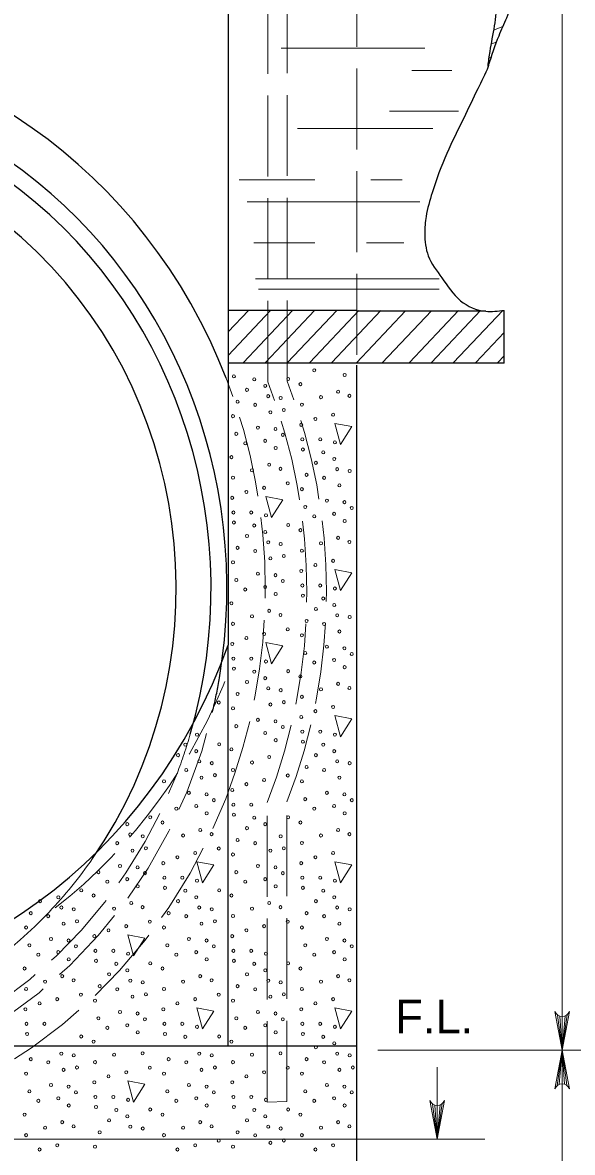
# Model space of a CAD drawing. Extents: x 1329.9 to 1363.9, y 715.5 to 737.5.
# Drawn here: x 1336.95 to 1339.48, y 718.65 to 723.85 of the extents above; entities that cross this region are included whole.
import ezdxf

# ---------------------------------------------------------------- set-up
doc = ezdxf.new("R2010")
doc.units = 0
doc.header["$LTSCALE"] = 0.062
doc.linetypes.add('LONG_DASHED', pattern=[7.5, 6, -1.5])
doc.layers.add('1', color=7, linetype='Continuous', lineweight=13)

msp = doc.modelspace()

# ---------------------------------------------------------------- linework, layer by layer
at = {"layer": '1', "linetype": 'LONG_DASHED'}
for p, q in [((1338.07492, 722.19533), (1338.07492, 728.64683)), ((1338.16467, 722.19817), (1338.16467, 728.66258)), ((1338.4845, 722.32), (1338.4845, 724.47975)), ((1338.07242, 718.88408), (1338.07242, 720.26208)), ((1338.16217, 718.88683), (1338.16217, 720.26483))]:
    msp.add_line(p, q, dxfattribs=at)
at = {"layer": '1'}
for p, q in [((1339.42875, 719.1235), (1339.42875, 725.87033)), ((1339.113, 723.81283), (1339.15642, 723.82967)), ((1338.1365, 723.73), (1338.797, 723.73)), ((1339.10158, 723.74783), (1339.12858, 723.75825)), ((1339.09125, 723.68325), (1339.104, 723.68817)), ((1338.73767, 723.6275), (1338.92117, 723.6275)), ((1339.087, 723.65125), (1339.09108, 723.65283)), ((1338.63417, 723.43925), (1338.95258, 723.43925)), ((1338.21075, 723.36067), (1338.83417, 723.36067)), ((1337.9435, 723.12492), (1338.29117, 723.12492)), ((1338.54842, 723.12492), (1338.69308, 723.12492)), ((1337.98067, 723.02283), (1338.77475, 723.02283)), ((1338.01033, 722.83417), (1338.29117, 722.83417)), ((1338.52942, 722.83417), (1338.70058, 722.83417)), ((1338.01775, 722.66917), (1338.8635, 722.66917)), ((1338.03258, 722.62208), (1338.8635, 722.62208)), ((1337.892, 722.3175), (1338.08733, 722.52442)), ((1337.892, 722.425), (1337.98592, 722.52442)), ((1337.892, 722.5205), (1337.89942, 722.52333)), ((1337.963, 722.28517), (1338.18892, 722.52442)), ((1338.0645, 722.28517), (1338.29042, 722.52442)), ((1338.16592, 722.28517), (1338.39192, 722.52442)), ((1338.2675, 722.28517), (1338.49342, 722.52442)), ((1338.36892, 722.28517), (1338.59492, 722.52442)), ((1338.48258, 722.28242), (1338.70858, 722.52167)), ((1338.60158, 722.28233), (1338.82758, 722.52158)), ((1338.7265, 722.28517), (1338.95233, 722.52433)), ((1338.82792, 722.28517), (1339.05383, 722.52433)), ((1338.92942, 722.28517), (1339.15533, 722.52433)), ((1339.031, 722.28517), (1339.16133, 722.42325)), ((1339.13242, 722.28517), (1339.16133, 722.31575)), ((1339.40742, 719.28467), (1339.42875, 719.1235)), ((1339.41792, 719.27925), (1339.42875, 719.1235)), ((1339.45225, 719.28658), (1339.42875, 719.1235)), ((1339.44242, 719.28042), (1339.42875, 719.1235)), ((1339.42875, 719.27758), (1339.42875, 719.1235)), ((1339.96792, 719.1235), (1338.58108, 719.1235)), ((1339.40517, 718.96033), (1339.42875, 719.1235)), ((1339.415, 718.9665), (1339.42875, 719.1235)), ((1339.42875, 719.1235), (1339.42875, 717.1515)), ((1339.42875, 718.96933), (1339.42875, 719.1235)), ((1339.4395, 718.96767), (1339.42875, 719.1235)), ((1339.45, 718.96225), (1339.42875, 719.1235)), ((1338.85383, 719.04492), (1338.85383, 718.71467)), ((1338.07242, 718.88408), (1338.16217, 718.88683)), ((1338.83258, 718.87592), (1338.85383, 718.71467)), ((1338.84308, 718.8705), (1338.85383, 718.71467)), ((1338.87742, 718.87783), (1338.85383, 718.71467)), ((1338.8675, 718.87167), (1338.85383, 718.71467)), ((1338.85383, 718.86883), (1338.85383, 718.71467)), ((1338.85383, 718.71467), (1336.15375, 718.71467)), ((1339.0725, 718.71467), (1338.84275, 718.71467))]:
    msp.add_line(p, q, dxfattribs=at)
at = {"layer": '1', "lineweight": 25}
for p, q in [((1337.892, 724.68033), (1337.892, 720.98492)), ((1338.4845, 722.52433), (1337.892, 722.52433)), ((1339.077, 722.52025), (1338.4845, 722.52025)), ((1339.16133, 722.28192), (1339.16133, 722.52433)), ((1339.16133, 722.28192), (1337.892, 722.28192)), ((1338.4845, 718.46475), (1338.4845, 722.27233)), ((1337.89108, 720.98492), (1337.89108, 719.143)), ((1332.86792, 719.143), (1338.4845, 719.143))]:
    msp.add_line(p, q, dxfattribs=at)
at = {"layer": '1'}
for points in [[(1338.38283, 722.00483), (1338.4085, 721.90758), (1338.46067, 721.98975)], [(1338.06558, 721.66908), (1338.09125, 721.57167), (1338.1435, 721.65383)], [(1338.38283, 721.33317), (1338.4085, 721.23583), (1338.46067, 721.318)], [(1338.06558, 720.99733), (1338.09125, 720.90008), (1338.1435, 720.98225)], [(1338.38283, 720.66158), (1338.4085, 720.56425), (1338.46067, 720.64642)], [(1337.74842, 719.98992), (1337.774, 719.89258), (1337.82633, 719.97475)], [(1338.38283, 719.98992), (1338.4085, 719.89258), (1338.46067, 719.97475)], [(1337.43125, 719.65408), (1337.45692, 719.55675), (1337.50908, 719.63892)], [(1337.74842, 719.31825), (1337.774, 719.22092), (1337.82633, 719.30317)], [(1338.38283, 719.31825), (1338.4085, 719.22092), (1338.46067, 719.30317)], [(1337.43125, 718.9825), (1337.45692, 718.88517), (1337.50908, 718.96725)]]:
    msp.add_lwpolyline(points, close=True, dxfattribs=at)
for points in [[(1339.46233, 719.30158), (1339.42875, 719.1235), (1339.39508, 719.30158)], [(1339.39508, 718.94533), (1339.42875, 719.1235), (1339.46233, 718.94533)], [(1338.8875, 718.89283), (1338.85383, 718.71467), (1338.82025, 718.89283)]]:
    msp.add_lwpolyline(points, dxfattribs=at)
at = {"layer": '1', "lineweight": 25}
for centre, major_axis, start_param, end_param in [((1335.66941, 721.24918), (0, -2.53448), 1.9607306, 4.343612), ((1335.66941, 721.24721), (0, -2.34775), 1.3944021, 4.9078414), ((1335.66941, 721.24578), (0, 2.27026), 4.4130472, 8.1227679), ((1335.66941, 721.24721), (0, 2.1004), 4.0791732, 8.4607413), ((1335.66522, 721.87991), (0, -2.52169), 5.0813574, 7.4910277)]:
    msp.add_ellipse(centre, major_axis=major_axis, ratio=0.944544, start_param=start_param, end_param=end_param, dxfattribs=at)
at = {"layer": '1'}
for centre in [(1337.91918, 722.22062), (1338.2884, 722.24872), (1338.42828, 722.22756), (1338.01259, 722.20702), (1338.06308, 722.17707), (1338.16844, 722.20881), (1338.22496, 722.18525), (1337.97913, 722.15894), (1338.07682, 722.12995), (1338.13418, 722.12172), (1338.31948, 722.12513), (1338.3983, 722.15049), (1338.45054, 722.13146), (1337.93604, 722.10426), (1338.01682, 722.09004), (1338.14872, 722.06648), (1338.23183, 722.09088), (1337.91463, 722.03804), (1338.08703, 722.05556), (1338.29373, 722.02534), (1338.37515, 722.04437), (1338.0294, 721.98549), (1338.11024, 721.97849), (1338.22871, 721.99814), (1337.93007, 721.95644), (1337.9712, 721.91289), (1338.06281, 721.9247), (1338.14391, 721.9519), (1338.23384, 721.93103), (1338.3161, 721.93103), (1338.38371, 721.91743), (1338.11108, 721.89174), (1338.23637, 721.8848), (1338.32979, 721.8712), (1337.90776, 721.84942), (1338.08111, 721.81466), (1338.29633, 721.82312), (1338.38028, 721.84125), (1337.91463, 721.75506), (1338.00228, 721.78931), (1338.13334, 721.79563), (1338.25324, 721.76843), (1338.33402, 721.75422), (1338.39402, 721.79412), (1338.45138, 721.7859), (1338.05795, 721.70854), (1338.1667, 721.72942), (1338.23183, 721.70222), (1338.40423, 721.71974), (1337.91151, 721.66231), (1337.97654, 721.68951), (1338.3466, 721.64966), (1337.91664, 721.5952), (1337.9989, 721.5952), (1338.24727, 721.62062), (1338.42743, 721.64267), (1338.46111, 721.61608), (1337.91918, 721.54897), (1338.06651, 721.5816), (1338.2884, 721.57707), (1338.38001, 721.58888), (1338.42828, 721.55591), (1338.01259, 721.53537), (1338.06308, 721.50543), (1338.16844, 721.53716), (1338.22496, 721.5136), (1337.97913, 721.48729), (1338.07682, 721.4583), (1338.13418, 721.45007), (1338.31948, 721.45349), (1338.3983, 721.47884), (1338.45054, 721.45981), (1337.93604, 721.43261), (1338.01682, 721.41839), (1338.14872, 721.39483), (1338.23183, 721.41923), (1337.91463, 721.3664), (1338.08703, 721.38392), (1338.29373, 721.35369), (1338.37515, 721.37272), (1337.93007, 721.28479), (1338.0294, 721.31384), (1338.11024, 721.30684), (1338.22871, 721.32649), (1337.9712, 721.24125), (1338.06281, 721.25306), (1338.14391, 721.28026), (1338.23384, 721.25938), (1338.3161, 721.25938), (1338.38371, 721.24578), (1337.90776, 721.17778), (1338.11108, 721.22009), (1338.23637, 721.21315), (1338.32979, 721.19955), (1338.08111, 721.14302), (1338.29633, 721.15147), (1338.38028, 721.16961), (1337.91463, 721.08341), (1338.00228, 721.11766), (1338.13334, 721.12399), (1338.25324, 721.09679), (1338.33402, 721.08257), (1338.39402, 721.12248), (1338.45138, 721.11425), (1338.05795, 721.0369), (1338.1667, 721.05778), (1338.23183, 721.03057), (1338.40423, 721.04809), (1337.91151, 720.99067), (1337.97654, 721.01787), (1338.3466, 720.97802), (1338.42743, 720.97102), (1337.91664, 720.92356), (1337.9989, 720.92356), (1338.24727, 720.94897), (1338.46111, 720.94444), (1337.91918, 720.87733), (1338.06651, 720.90996), (1338.2884, 720.90542), (1338.38001, 720.91723), (1338.42828, 720.88427), (1337.97913, 720.81565), (1338.01259, 720.86373), (1338.06308, 720.83378), (1338.16844, 720.86552), (1338.22496, 720.84195), (1338.07682, 720.78666), (1338.13418, 720.77843), (1338.31948, 720.78184), (1338.3983, 720.8072), (1338.45054, 720.78817), (1337.8495, 720.72195), (1337.93604, 720.76096), (1338.08703, 720.71227), (1338.14872, 720.72318), (1338.23183, 720.74759), (1337.91463, 720.69475), (1338.29373, 720.68205), (1338.37515, 720.70108), (1337.93007, 720.61315), (1338.0294, 720.6422), (1338.11024, 720.6352), (1338.14391, 720.60861), (1338.22871, 720.65484), (1337.74932, 720.57414), (1338.06281, 720.58141), (1338.23384, 720.58774), (1338.3161, 720.58774), (1338.38371, 720.57414), (1337.69539, 720.5279), (1337.85124, 720.52969), (1337.90776, 720.50613), (1338.11108, 720.54845), (1338.23637, 720.5415), (1338.32979, 720.5279), (1337.66193, 720.47983), (1337.74588, 720.49796), (1337.75962, 720.45083), (1338.08111, 720.47137), (1338.29633, 720.47983), (1338.38028, 720.49796), (1338.39402, 720.45083), (1337.69962, 720.41093), (1337.81698, 720.4426), (1337.91463, 720.41177), (1338.00228, 720.44602), (1338.25324, 720.42514), (1338.33402, 720.41093), (1338.45138, 720.4426), (1337.59743, 720.35893), (1337.76983, 720.37645), (1337.83152, 720.38736), (1338.05795, 720.36525), (1338.1667, 720.38613), (1338.23183, 720.35893), (1338.40423, 720.37645), (1337.7122, 720.30637), (1337.79304, 720.29938), (1337.91151, 720.31902), (1337.97654, 720.34622), (1338.3466, 720.30637), (1338.42743, 720.29938), (1337.74561, 720.24559), (1337.82671, 720.27279), (1337.91664, 720.25191), (1337.9989, 720.25191), (1338.24727, 720.27732), (1338.38001, 720.24559), (1338.46111, 720.27279), (1337.53404, 720.19387), (1337.654, 720.23378), (1337.79388, 720.21262), (1337.91918, 720.20568), (1338.01259, 720.19208), (1338.16844, 720.19387), (1338.2884, 720.23378), (1338.42828, 720.21262), (1337.42868, 720.16214), (1337.59056, 720.17031), (1337.97913, 720.144), (1338.06308, 720.16214), (1338.22496, 720.17031), (1337.44242, 720.11501), (1337.49978, 720.10678), (1337.68508, 720.1102), (1337.76391, 720.13555), (1337.81614, 720.11652), (1337.93604, 720.08932), (1338.13418, 720.10678), (1338.31948, 720.1102), (1338.3983, 720.13555), (1338.45054, 720.11652), (1337.38242, 720.0751), (1337.45263, 720.04062), (1337.51432, 720.05154), (1337.8495, 720.05031), (1338.01682, 720.0751), (1338.08703, 720.04062), (1338.14872, 720.05154), (1338.23183, 720.07594), (1337.59431, 719.9832), (1337.65934, 720.0104), (1337.74075, 720.02943), (1337.91463, 720.02311), (1338.22871, 719.9832), (1338.29373, 720.0104), (1338.37515, 720.02943), (1337.29567, 719.9415), (1337.395, 719.97055), (1337.47584, 719.96355), (1337.50951, 719.93697), (1337.93007, 719.9415), (1338.0294, 719.97055), (1338.11024, 719.96355), (1338.14391, 719.93697), (1337.3368, 719.89796), (1337.42841, 719.90977), (1337.59944, 719.91609), (1337.6817, 719.91609), (1337.74932, 719.90249), (1337.9712, 719.89796), (1338.06281, 719.90977), (1338.23384, 719.91609), (1338.3161, 719.91609), (1338.38371, 719.90249), (1337.21684, 719.85805), (1337.27336, 719.83449), (1337.47668, 719.8768), (1337.60198, 719.86986), (1337.69539, 719.85626), (1337.85124, 719.85805), (1337.90776, 719.83449), (1338.11108, 719.8768), (1338.23637, 719.86986), (1338.32979, 719.85626), (1337.02753, 719.80818), (1337.11148, 719.82631), (1337.12523, 719.77919), (1337.44671, 719.79973), (1337.49894, 719.7807), (1337.66193, 719.80818), (1337.74588, 719.82631), (1337.75962, 719.77919), (1338.08111, 719.79973), (1338.13334, 719.7807), (1338.29633, 719.80818), (1338.38028, 719.82631), (1338.39402, 719.77919), (1336.98444, 719.7535), (1337.06522, 719.73928), (1337.18259, 719.77096), (1337.36788, 719.77437), (1337.61884, 719.7535), (1337.69962, 719.73928), (1337.81698, 719.77096), (1337.91463, 719.74012), (1338.00228, 719.77437), (1338.25324, 719.7535), (1338.33402, 719.73928), (1338.45138, 719.77096), (1336.96303, 719.68728), (1337.13543, 719.7048), (1337.19712, 719.71572), (1337.34214, 719.67458), (1337.42355, 719.69361), (1337.5323, 719.71449), (1337.59743, 719.68728), (1337.76983, 719.7048), (1337.83152, 719.71572), (1337.97654, 719.67458), (1338.05795, 719.69361), (1338.1667, 719.71449), (1338.23183, 719.68728), (1338.40423, 719.7048), (1337.0778, 719.63473), (1337.15864, 719.62773), (1337.27711, 719.64738), (1337.7122, 719.63473), (1337.79304, 719.62773), (1337.91151, 719.64738), (1338.3466, 719.63473), (1338.42743, 719.62773), (1336.97847, 719.60568), (1337.11122, 719.57394), (1337.19231, 719.60114), (1337.28224, 719.58027), (1337.3645, 719.58027), (1337.61287, 719.60568), (1337.74561, 719.57394), (1337.82671, 719.60114), (1337.91664, 719.58027), (1337.9989, 719.58027), (1338.24727, 719.60568), (1338.38001, 719.57394), (1338.46111, 719.60114), (1337.0196, 719.56213), (1337.15948, 719.54098), (1337.28478, 719.53404), (1337.37819, 719.52044), (1337.43212, 719.56667), (1337.53404, 719.52223), (1337.654, 719.56213), (1337.79388, 719.54098), (1337.91918, 719.53404), (1338.01259, 719.52044), (1338.06651, 719.56667), (1338.16844, 719.52223), (1338.2884, 719.56213), (1338.42828, 719.54098), (1336.95616, 719.49866), (1337.12951, 719.46391), (1337.34473, 719.47236), (1337.42868, 719.49049), (1337.59056, 719.49866), (1337.76391, 719.46391), (1337.97913, 719.47236), (1338.06308, 719.49049), (1338.22496, 719.49866), (1338.3983, 719.46391), (1337.05068, 719.43855), (1337.18174, 719.44488), (1337.30164, 719.41767), (1337.44242, 719.44336), (1337.49978, 719.43514), (1337.68508, 719.43855), (1337.81614, 719.44488), (1337.93604, 719.41767), (1338.07682, 719.44336), (1338.13418, 719.43514), (1338.31948, 719.43855), (1338.45054, 719.44488), (1336.96303, 719.4043), (1337.2151, 719.37866), (1337.38242, 719.40346), (1337.45263, 719.36898), (1337.51432, 719.37989), (1337.59743, 719.4043), (1337.8495, 719.37866), (1338.01682, 719.40346), (1338.08703, 719.36898), (1338.14872, 719.37989), (1338.23183, 719.4043), (1336.95991, 719.31155), (1337.02494, 719.33876), (1337.10635, 719.35779), (1337.28023, 719.35146), (1337.59431, 719.31155), (1337.65934, 719.33876), (1337.74075, 719.35779), (1337.91463, 719.35146), (1338.22871, 719.31155), (1338.29373, 719.33876), (1338.37515, 719.35779), (1337.29567, 719.26986), (1337.395, 719.2989), (1337.47584, 719.29191), (1337.50951, 719.26532), (1337.93007, 719.26986), (1338.0294, 719.2989), (1338.11024, 719.29191), (1338.14391, 719.26532), (1336.96504, 719.24445), (1337.0473, 719.24445), (1337.3368, 719.22631), (1337.42841, 719.23812), (1337.47668, 719.20515), (1337.59944, 719.24445), (1337.6817, 719.24445), (1337.74932, 719.23084), (1337.9712, 719.22631), (1338.06281, 719.23812), (1338.11108, 719.20515), (1338.23384, 719.24445), (1338.3161, 719.24445), (1338.38371, 719.23084), (1336.96758, 719.19821), (1337.21684, 719.1864), (1337.27336, 719.16284), (1337.60198, 719.19821), (1337.69539, 719.18461), (1337.85124, 719.1864), (1337.90776, 719.16284), (1338.23637, 719.19821), (1338.32979, 719.18461), (1338.38028, 719.15467), (1337.12523, 719.10754), (1337.36788, 719.10273), (1337.49894, 719.10905), (1337.75962, 719.10754), (1338.00228, 719.10273), (1338.13334, 719.10905), (1338.29633, 719.13653), (1338.39402, 719.10754), (1336.98444, 719.08185), (1337.06522, 719.06763), (1337.18259, 719.09931), (1337.28023, 719.06847), (1337.61884, 719.08185), (1337.69962, 719.06763), (1337.81698, 719.09931), (1337.91463, 719.06847), (1338.25324, 719.08185), (1338.33402, 719.06763), (1338.45138, 719.09931), (1336.96303, 719.01564), (1337.13543, 719.03316), (1337.19712, 719.04407), (1337.34214, 719.00293), (1337.42355, 719.02196), (1337.5323, 719.04284), (1337.59743, 719.01564), (1337.76983, 719.03316), (1337.83152, 719.04407), (1337.97654, 719.00293), (1338.05795, 719.02196), (1338.1667, 719.04284), (1338.23183, 719.01564), (1338.40423, 719.03316), (1338.46592, 719.04407), (1337.0778, 718.96308), (1337.15864, 718.95609), (1337.27711, 718.97573), (1337.7122, 718.96308), (1337.79304, 718.95609), (1337.91151, 718.97573), (1338.3466, 718.96308), (1338.42743, 718.95609), (1336.97847, 718.93403), (1337.11122, 718.9023), (1337.19231, 718.9295), (1337.28224, 718.90862), (1337.3645, 718.90862), (1337.43212, 718.89502), (1337.61287, 718.93403), (1337.74561, 718.9023), (1337.82671, 718.9295), (1337.91664, 718.90862), (1337.9989, 718.90862), (1338.06651, 718.89502), (1338.24727, 718.93403), (1338.38001, 718.9023), (1338.46111, 718.9295), (1337.0196, 718.89049), (1337.15948, 718.86933), (1337.28478, 718.86239), (1337.37819, 718.84879), (1337.53404, 718.85058), (1337.654, 718.89049), (1337.79388, 718.86933), (1337.91918, 718.86239), (1338.01259, 718.84879), (1338.16844, 718.85058), (1338.2884, 718.89049), (1338.42828, 718.86933), (1336.95616, 718.82702), (1337.12951, 718.79226), (1337.34473, 718.80071), (1337.42868, 718.81885), (1337.59056, 718.82702), (1337.76391, 718.79226), (1337.97913, 718.80071), (1338.06308, 718.81885), (1338.22496, 718.82702), (1338.3983, 718.79226), (1337.05068, 718.76691), (1337.18174, 718.77323), (1337.30164, 718.74603), (1337.44242, 718.77172), (1337.49978, 718.76349), (1337.68508, 718.76691), (1337.81614, 718.77323), (1337.93604, 718.74603), (1338.07682, 718.77172), (1338.13418, 718.76349), (1338.31948, 718.76691), (1338.45054, 718.77323), (1336.96303, 718.73265), (1337.10635, 718.68614), (1337.59743, 718.73265), (1337.74075, 718.68614), (1337.8495, 718.70702), (1338.01682, 718.73181), (1338.08703, 718.69733), (1338.14872, 718.70825), (1338.23183, 718.73265), (1338.37515, 718.68614), (1337.02494, 718.66711), (1337.28023, 718.67982), (1337.65934, 718.66711), (1337.91463, 718.67982), (1338.29373, 718.66711)]:
    msp.add_ellipse(centre, major_axis=(0, 0.00718), ratio=0.944544, dxfattribs=at)
at = {"layer": '1', "linetype": 'LONG_DASHED'}
for centre, major_axis, start_param, end_param in [((1335.66941, 721.24918), (0, -2.53448), 1.1781136, 1.9607306), ((1335.86073, 721.23193), (0, -2.53448), 1.1781136, 1.9607306), ((1335.95045, 721.2347), (0, -2.53448), 1.1781136, 1.9607306), ((1335.67733, 721.81767), (0, -2.53448), 0.6349589, 1.1921317), ((1335.66941, 721.24721), (0, -2.34775), 4.9078414, 7.6167139), ((1335.66941, 721.24578), (0, 2.27026), 4.328587, 4.4130472), ((1335.66941, 721.24578), (0, 2.27026), 1.91212, 4.328587), ((1335.66941, 721.24918), (0, -2.53448), 5.0823137, 7.4612989), ((1335.66941, 721.24721), (0, 2.1004), 3.9243143, 4.0791732), ((1335.66941, 721.24721), (0, 2.1004), 3.5617964, 3.9243143)]:
    msp.add_ellipse(centre, major_axis=major_axis, ratio=0.944544, start_param=start_param, end_param=end_param, dxfattribs=at)
at = {"layer": '1', "linetype": 'LONG_DASHED', "lineweight": 25}
msp.add_ellipse((1335.66941, 721.24721), major_axis=(0, -2.34775), ratio=0.944544, start_param=1.3335286, end_param=1.3944021, dxfattribs=at)
at = {"layer": '1'}
for centre, major_axis in [((1339.42872, 719.31601), (0, -0.03844)), ((1339.42872, 718.93091), (0, 0.03844)), ((1338.85385, 718.90726), (0, -0.03844))]:
    msp.add_ellipse(centre, major_axis=major_axis, ratio=0.944544, start_param=5.0978942, end_param=7.4685073, dxfattribs=at)
at = {"layer": '1', "lineweight": 25}
for points in [[(1339.09042, 723.651), (1339.13833, 723.787), (1339.17375, 723.86975), (1339.22483, 724.07217), (1339.22725, 724.15625), (1339.21867, 724.26008), (1339.1965, 724.373), (1339.16217, 724.46625), (1339.08633, 724.56467), (1338.98608, 724.64475), (1338.93308, 724.66717), (1338.83592, 724.68033)], [(1338.83592, 724.46725), (1338.89217, 724.4555), (1338.97292, 724.4095), (1339.03275, 724.34133), (1339.08175, 724.24158), (1339.09883, 724.16925), (1339.1185, 724.08517), (1339.12725, 723.94992), (1339.11625, 723.83167), (1339.09558, 723.71467), (1339.08633, 723.647)], [(1339.09042, 723.651), (1339.08833, 723.645), (1339.04075, 723.54242), (1338.97617, 723.40842), (1338.89808, 723.24542), (1338.83108, 723.06525), (1338.80308, 722.95617), (1338.797, 722.87733), (1338.81292, 722.77492), (1338.87542, 722.67383), (1338.961, 722.56875), (1339.077, 722.52025), (1339.16133, 722.52433)]]:
    msp.add_spline(points, degree=3, dxfattribs=at)

# ---------------------------------------------------------------- texts
at = {"layer": '1'}
msp.add_text('F.L.', height=0.156, dxfattribs=at).set_placement((1338.66067, 719.20025))

doc.saveas('drawing.dxf')
